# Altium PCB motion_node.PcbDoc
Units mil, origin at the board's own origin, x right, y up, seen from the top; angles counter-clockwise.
Board outline 1965 x 1965 mil, 2 copper layers (Top Layer, Bottom Layer); 90 components, 96 nets, 377 pads, 0 vias.
Unrouted connection lines stored in the file: 226.
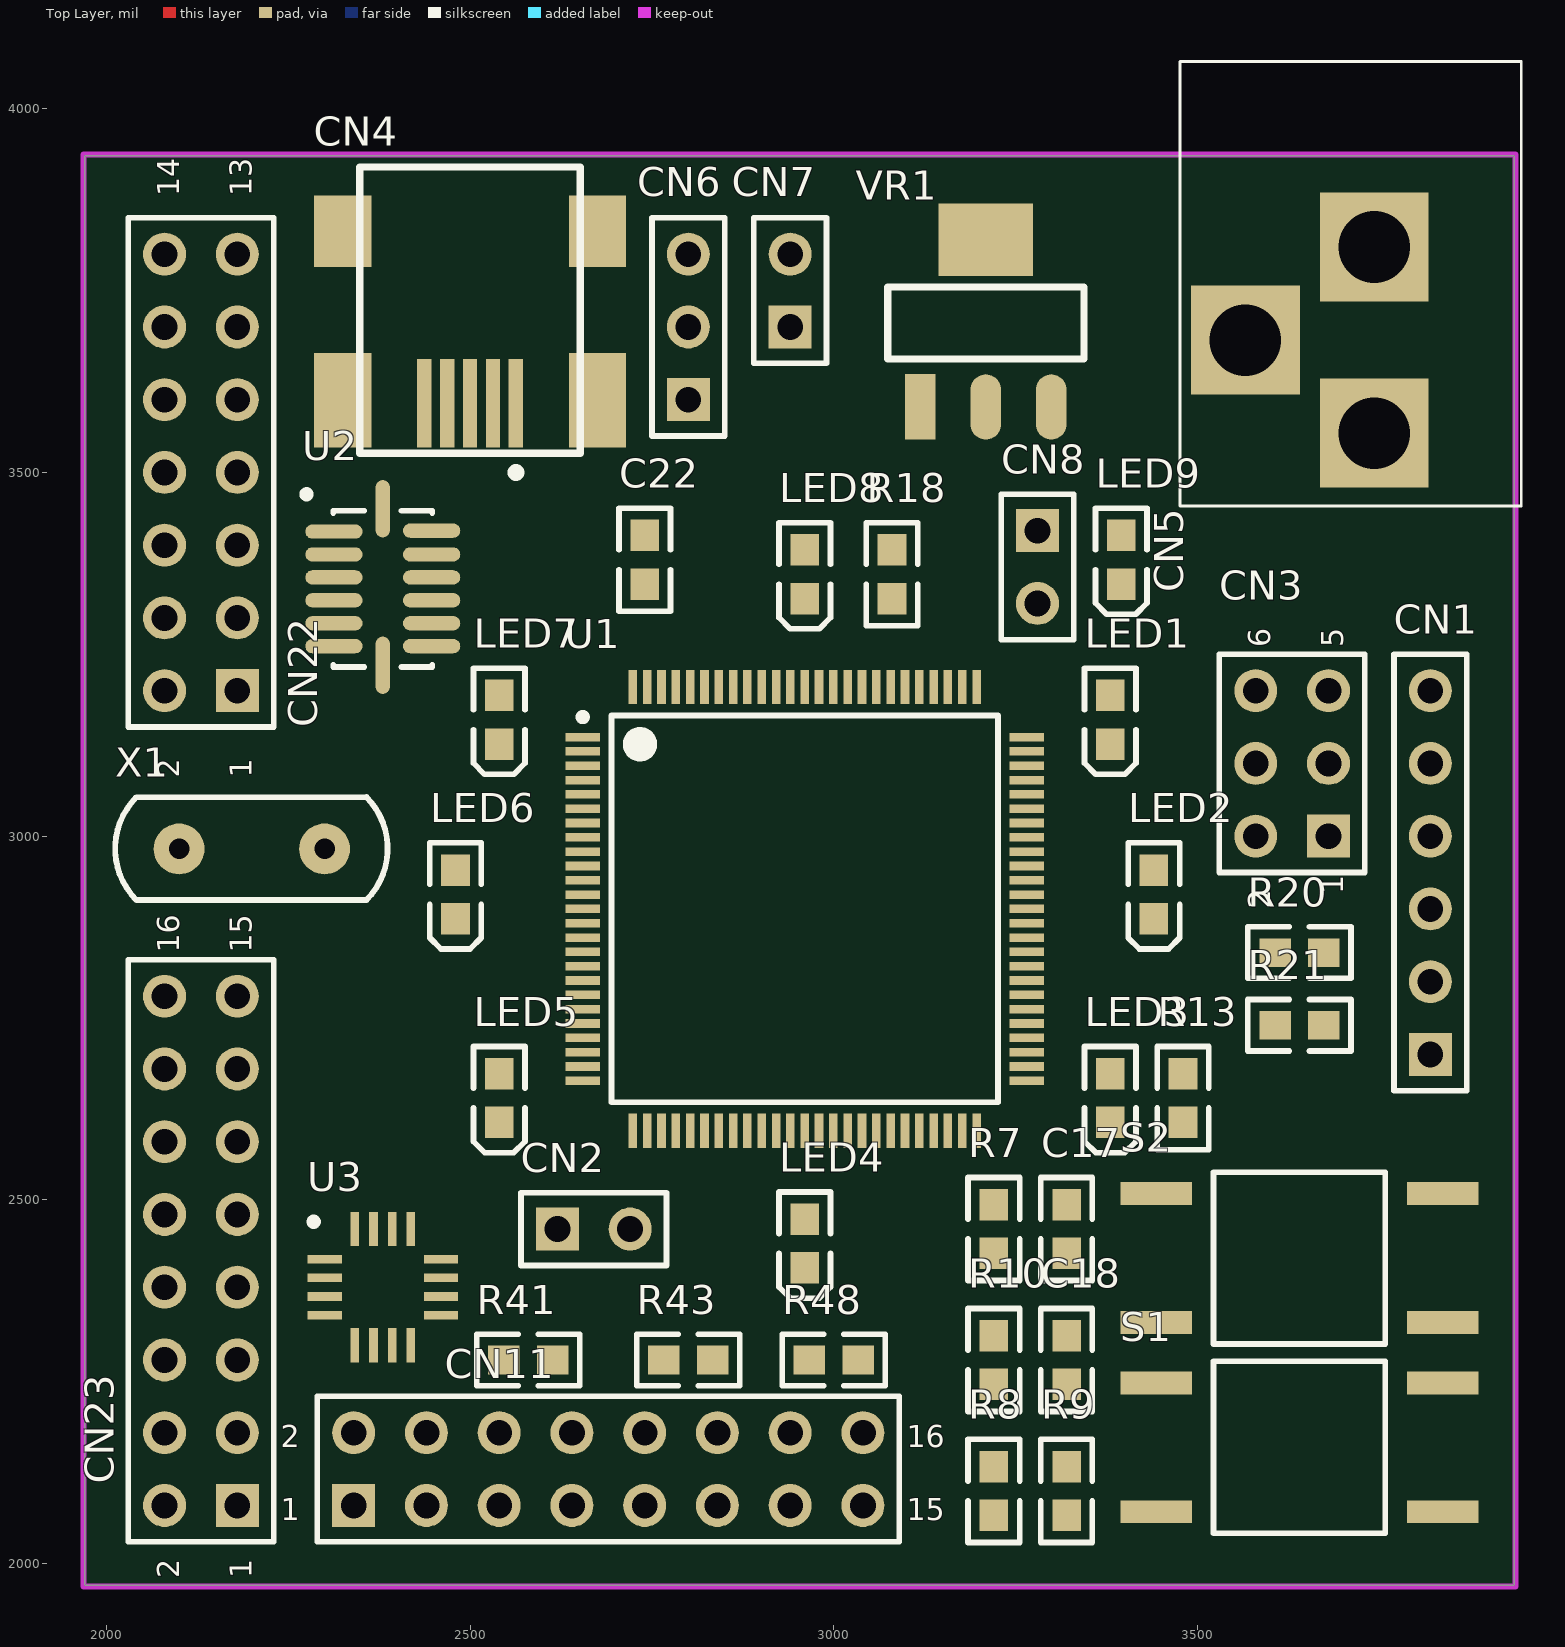
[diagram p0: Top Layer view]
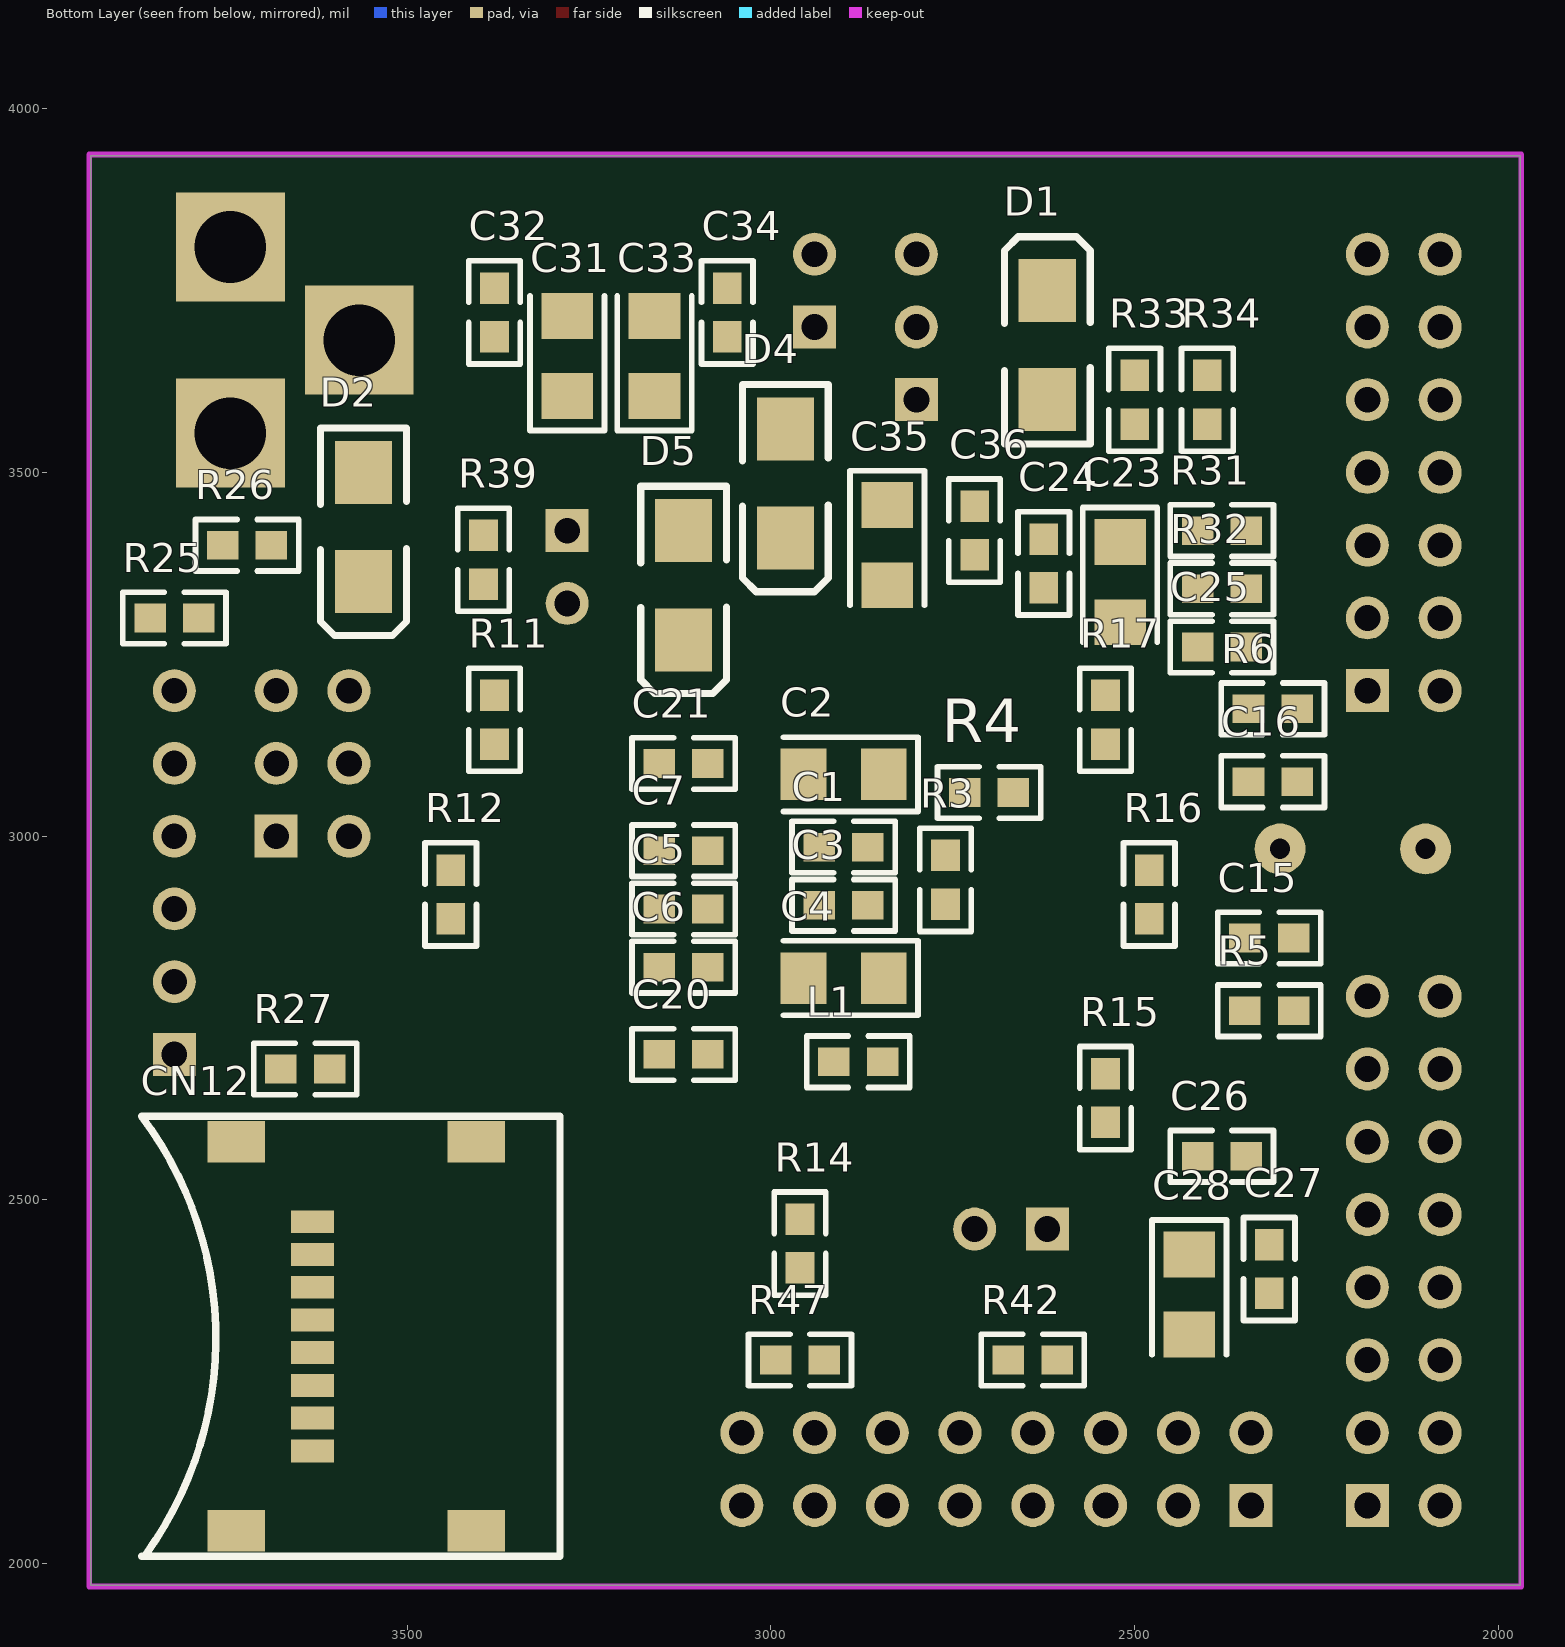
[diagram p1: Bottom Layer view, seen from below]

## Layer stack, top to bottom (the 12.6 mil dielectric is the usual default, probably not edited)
Top Layer: signal copper 1.4
Dielectric: dielectric 12.6, FR-4, Dk 4.8
Bottom Layer: signal copper 1.4

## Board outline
1970,3935 1970,1970 3935,1970 3935,3935

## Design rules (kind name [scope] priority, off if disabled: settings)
Clearance [All] p1: gap=6
ComponentClearance [All] p1: gap=0 collisioncheckmode=3 verticalgap=10 showdistances=FALSE
PolygonConnect [All] p1: connectstyle=Relief reliefconductorwidth=10 reliefentries=4 polygonreliefangle="90 Angle"
RoutingVias [All] p1: holewidth=28 width=50 viastyle="Through Hole" minholewidth=28 minwidth=50 maxholewidth=28 maxwidth=50
SilkscreenOverComponentPads [All] p1: minsilkscreentomaskgap=10
SolderMaskExpansion [All] p1: expansion=4
Width [All] p1: maxlimit=40 minlimit=6 preferedwidth=6
26 further rules are at their usual default settings.

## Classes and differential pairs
net class LED[8..1]: LED1 LED2 LED3 LED4 LED5 LED6 LED7 LED8
component class stm32f407: C1 C2 C3 C4 C5 C6 C7 C15 C16 C17 C18 C20 C21 CN1 CN2 CN3 L1 R3 R4 R5 R6 R7 R8 R9 R10 R20 R21 R25 R26 R27 S1 S2 U1 X1
component class sensors: C22 C23 C24 C25 C26 C27 C28 CN22 CN23 R31 R32 U2 U3
component class power: C31 C32 C33 C34 C35 C36 CN4 CN5 CN6 CN7 CN8 D1 D2 D4 D5 LED9 R33 R34 R39 VR1
component class others: CN11 CN12 LED1 LED2 LED3 LED4 LED5 LED6 LED7 LED8 R11 R12 R13 R14 R15 R16 R17 R18 R41 R42 R43 R47 R48

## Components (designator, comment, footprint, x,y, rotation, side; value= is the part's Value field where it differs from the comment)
C1 "Cap Semi" C1608-0603 2900,2985 r180 bottom
C2 "Cap Pol3" CC3216-1206 2900,3085 r0 bottom
C3 "Cap Semi" C1608-0603 2900,2905 r180 bottom
C4 "Cap Pol3" CC3216-1206 2900,2805 r0 bottom
C5 "Cap Semi" C1608-0603 3120,2900 r0 bottom
C6 "Cap Semi" C1608-0603 3120,2820 r0 bottom
C7 "Cap Semi" C1608-0603 3120,2980 r0 bottom
C15 "Cap Semi" C1608-0603 2315,2860 r180 bottom
C16 "Cap Semi" C1608-0603 2310,3075 r180 bottom
C17 "Cap Semi" C1608-0603 3320,2460 r270 top
C18 "Cap Semi" C1608-0603 3320,2280 r90 top
C20 "Cap Semi" C1608-0603 3120,2700 r0 bottom
C21 "Cap Semi" C1608-0603 3120,3100 r0 bottom
C22 "Cap Semi" C1608-0603 2740,3380 r270 top
C23 "Cap Pol3" CC3216-1206 2520,3349.31 r270 bottom
C24 "Cap Semi" C1608-0603 2625,3375 r270 bottom
C25 "Cap Semi" C1608-0603 2380,3260 r0 bottom
C26 "Cap Semi" C1608-0603 2380,2560 r180 bottom
C27 "Cap Semi" C1608-0603 2315,2405 r270 bottom
C28 "Cap Pol3" CC3216-1206 2425,2370 r270 bottom
C31 "Cap Pol3" CC3216-1206 3280,3660 r90 bottom
C32 "Cap Semi" C1608-0603 3380,3720 r270 bottom
C33 "Cap Pol3" CC3216-1206 3160,3660 r90 bottom
C34 "Cap Semi" C1608-0603 3060,3720 r270 bottom
C35 "Cap Pol3" CC3216-1206 2840,3400 r270 bottom
C36 "Cap Semi" C1608-0603 2720,3420 r90 bottom
CN1 "Header 6" HDR1X6 3820,2700 r90 top
CN2 "Header 2" HDR1X2 2620,2460 r0 top
CN3 "Header 3X2" HDR2X3 3680,3000 r90 top
CN4 "mini USB Type B" "mini USB Type B" 2500,3920 r180 top
CN5 "Power_Jack" POWER_JACK 3700,3840 r90 top
CN6 "Header 3" HDR1X3 2800,3600 r90 top
CN7 "Header 2" HDR1X2 2940,3700 r90 top
CN8 "Header 2" HDR1X2 3280,3420 r270 top
CN11 "Header 8X2" HDR2X8 2340,2080 r0 top
CN12 "micro SD" "micro SD" 3520,2320 r0 bottom
CN22 "Header 7X2" HDR2X7 2180,3200 r90 top
CN23 "Header 8X2" HDR2X8 2180,2080 r90 top
D1 "Diode" IN5817 2520,3600 r90 bottom
D2 "Diode" IN5817 3660,3500 r270 bottom
D4 "Diode" IN5817 3080,3560 r270 bottom
D5 "Diode" IN5817 3220,3420 r270 bottom
L1 "Inductor" R1608-0603 2880,2690 r180 bottom
LED1 "" D1608-0603 3380,3160 r270 top
LED2 "" D1608-0603 3440,2920 r270 top
LED3 "" D1608-0603 3380,2640 r270 top
LED4 "" D1608-0603 2960,2440 r270 top
LED5 "" D1608-0603 2540,2640 r270 top
LED6 "" D1608-0603 2480,2920 r270 top
LED7 "" D1608-0603 2540,3160 r270 top
LED8 "" D1608-0603 2960,3360 r270 top
LED9 "" D1608-0603 3395,3380 r270 top
R3 "Res Semi" R1608-0603 2760,2940 r270 bottom
R4 "Res Semi" R1608-0603 2700,3060 r180 bottom
R5 "Res Semi" R1608-0603 2315,2760 r180 bottom
R6 "Res Semi" R1608-0603 2310,3175 r180 bottom
R7 "Res Semi" R1608-0603 3220,2460 r270 top
R8 "Res Semi" R1608-0603 3220,2100 r90 top
R9 "Res Semi" R1608-0603 3320,2100 r270 top
R10 "Res Semi" R1608-0603 3220,2280 r270 top
R11 "Res Semi" R1608-0603 3380,3160 r90 bottom
R12 "Res Semi" R1608-0603 3440,2920 r90 bottom
R13 "Res Semi" R1608-0603 3480,2640 r90 top
R14 "Res Semi" R1608-0603 2960,2440 r90 bottom
R15 "Res Semi" R1608-0603 2540,2640 r90 bottom
R16 "Res Semi" R1608-0603 2480,2920 r90 bottom
R17 "Res Semi" R1608-0603 2540,3160 r90 bottom
R18 "Res Semi" R1608-0603 3080,3360 r90 top
R20 "Res Semi" R1608-0603 3640,2840 r180 top
R21 "Res Semi" R1608-0603 3640,2740 r180 top
R25 "Res Semi" R1608-0603 3820,3300 r180 bottom
R26 "Res Semi" R1608-0603 3720,3400 r0 bottom
R27 "Res Semi" R1608-0603 3640,2680 r180 bottom
R31 "Res Semi" R1608-0603 2380,3420 r180 bottom
R32 "Res Semi" R1608-0603 2380,3340 r180 bottom
R33 "Res Semi" R1608-0603 2500,3600 r270 bottom
R34 "Res Semi" R1608-0603 2400,3600 r270 bottom
R39 "Res Semi" R1608-0603 3395,3380 r90 bottom
R41 "Res Semi" R1608-0603 2580,2280 r180 top
R42 "Res Semi" R1608-0603 2640,2280 r180 bottom
R43 "Res Semi" R1608-0603 2800,2280 r180 top
R47 "Res Semi" R1608-0603 2960,2280 r0 bottom
R48 "Res Semi" R1608-0603 3000,2280 r180 top
S1 "Switch6X6" Switch6X6 3640,2160 r0 top
S2 "Switch6X6" Switch6X6 3640,2420 r0 top
U1 "STM32F407VGT6" LQFP100_V 2960,2900 r0 top locked
U2 "LSM303DLHC" LGA14-3X5X1_N 2380,3340 r0 top locked
U3 "L3GD20" LGA16-4X4X1 2380,2380 r0 top locked
VR1 "AMS1117" AMS1117 3260,3840 r90 top
X1 "8MHz" XTAL-0.2 2180,3140 r0 top

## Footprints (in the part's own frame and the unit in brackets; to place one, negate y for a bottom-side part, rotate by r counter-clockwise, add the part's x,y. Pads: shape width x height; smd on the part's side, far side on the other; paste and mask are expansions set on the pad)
AMS1117 [mil]
  rect 90x42 smd: 1(-250,141)
  oval 90x42 smd: 2(-250,51) 3(-250,-39)
  rect 100x130 smd: 4(-20,51)
  silkscreen extent -184,-84 -85,186
C1608-0603 [mm]
  rect 1.1x1 smd: 1(-0.85,0) 2(0.85,0)
  silkscreen extent -1.8,-0.9 1.8,0.9
CC3216-1206 [mm]
  rect 1.6x1.8 smd: 1(-1.4,0) 2(1.4,0)
  silkscreen extent -2.6,-1.3 2.1,1.3
D1608-0603 [mm]
  rect 1.1x1 smd: 1(-0.85,0) 2(0.85,0)
  silkscreen extent -1.8,-0.9 1.91,0.9
HDR1X2 [mm] "Connector; Header; 2 Position"
  rect 1.5x1.5 hole 0.9: 1(0,0)
  round 1.5 hole 0.9: 2(2.54,0)
  silkscreen extent -1.27,-1.27 3.81,1.27
HDR1X3 [mm] "Connector; Header; 3 Position"
  rect 1.5x1.5 hole 0.9: 1(0,0)
  round 1.5 hole 0.9: 2(2.54,0) 3(5.08,0)
  silkscreen extent -1.27,-1.27 6.35,1.27
HDR1X6 [mm] "Connector; Header; 6 Position"
  rect 1.5x1.5 hole 0.9: 1(0,0)
  round 1.5 hole 0.9: 2(2.54,0) 3(5.08,0) 4(7.62,0) 5(10.16,0) 6(12.7,0)
  silkscreen extent -1.27,-1.27 13.97,1.27
HDR2X3 [mm] "Connector; Header; 3x2 Position"
  rect 1.5x1.5 hole 0.9: 1(0,0)
  round 1.5 hole 0.9: 2(0,2.54) 3(2.54,0) 4(2.54,2.54) 5(5.08,0) 6(5.08,2.54)
  silkscreen extent -1.27,-1.27 6.35,3.81
HDR2X7 [mm] "Connector; Header; 7x2 Position"
  rect 1.5x1.5 hole 0.9: 1(0,0)
  round 1.5 hole 0.9: 2(0,2.54) 3(2.54,0) 4(2.54,2.54) 5(5.08,0) 6(5.08,2.54) 7(7.62,0) 8(7.62,2.54) 9(10.16,0) 10(10.16,2.54) 11(12.7,0) 12(12.7,2.54) 13(15.24,0) 14(15.24,2.54)
  silkscreen extent -1.27,-1.27 16.51,3.81
HDR2X8 [mm] "Connector; Header; 8x2 Position"
  rect 1.5x1.5 hole 0.9: 1(0,0)
  round 1.5 hole 0.9: 2(0,2.54) 3(2.54,0) 4(2.54,2.54) 5(5.08,0) 6(5.08,2.54) 7(7.62,0) 8(7.62,2.54) 9(10.16,0) 10(10.16,2.54) 11(12.7,0) 12(12.7,2.54) 13(15.24,0) 14(15.24,2.54) 15(17.78,0) 16(17.78,2.54)
  silkscreen extent -1.27,-1.27 19.05,3.81
IN5817 [mm]
  rect 2.2x2 smd: 1(0,2.54) 2(3.81,2.54)
  silkscreen extent -1.55,1.04 5.69,4.04
LGA14-3X5X1_N [mm] "PQFN, 14-Leads, Body 3x5mm, Pitch 0.8mm, IPC Medium Density"
  oval 2x0.5 smd: 1(-1.706,2) 2(-1.706,1.2) 3(-1.706,0.4) 4(-1.706,-0.4) 5(-1.706,-1.2) 6(-1.706,-2) 8(1.706,-2) 9(1.706,-1.2) 10(1.706,-0.4) 11(1.706,0.4) 12(1.706,1.2) 13(1.706,2.032)
  oval 0.5x2 smd: 7(0,-2.667) 14(0,2.794)
  silkscreen extent -2.79,-2.72 1.73,3.43, body extent -1.57,-2.57 1.58,2.58, height 1
LGA16-4X4X1 [mm]
  rect 1.2x0.3 smd: 1(-2.032,0.975) 2(-2.032,0.325) 3(-2.032,-0.325) 4(-2.032,-0.975) 9(2.032,-0.975) 10(2.032,-0.325) 11(2.032,0.325) 12(2.032,0.975)
  rect 0.3x1.2 smd: 5(-0.975,-2.032) 6(-0.325,-2.032) 7(0.325,-2.032) 8(0.975,-2.032) 13(0.975,2.032) 14(0.325,2.032) 15(-0.325,2.032) 16(-0.975,2.032)
  silkscreen extent -2.54,2.16 -2.29,2.41
LQFP100_V [mm] "Thin QFP, 100-Leads, Body 14x14mm, Pitch 0.5mm, ST Recommended"
  rect 1.2x0.3 smd: 1(-7.75,6) 2(-7.75,5.5) 3(-7.75,5) 4(-7.75,4.5) 5(-7.75,4) 6(-7.75,3.5) 7(-7.75,3) 8(-7.75,2.5) 9(-7.75,2) 10(-7.75,1.5) 11(-7.75,1) 12(-7.75,0.5) 13(-7.75,0) 14(-7.75,-0.5) 15(-7.75,-1) 16(-7.75,-1.5) 17(-7.75,-2) 18(-7.75,-2.5) 19(-7.75,-3) 20(-7.75,-3.5) 21(-7.75,-4) 22(-7.75,-4.5) 23(-7.75,-5) 24(-7.75,-5.5) 25(-7.75,-6) 51(7.75,-6) 52(7.75,-5.5) 53(7.75,-5) 54(7.75,-4.5) 55(7.75,-4) 56(7.75,-3.5) 57(7.75,-3) 58(7.75,-2.5) 59(7.75,-2) 60(7.75,-1.5) 61(7.75,-1) 62(7.75,-0.5) 63(7.75,0) 64(7.75,0.5) 65(7.75,1) 66(7.75,1.5) 67(7.75,2) 68(7.75,2.5) 69(7.75,3) 70(7.75,3.5) 71(7.75,4) 72(7.75,4.5) 73(7.75,5) 74(7.75,5.5) 75(7.75,6)
  rect 0.3x1.2 smd: 26(-6,-7.75) 27(-5.5,-7.75) 28(-5,-7.75) 29(-4.5,-7.75) 30(-4,-7.75) 31(-3.5,-7.75) 32(-3,-7.75) 33(-2.5,-7.75) 34(-2,-7.75) 35(-1.5,-7.75) 36(-1,-7.75) 37(-0.5,-7.75) 38(0,-7.75) 39(0.5,-7.75) 40(1,-7.75) 41(1.5,-7.75) 42(2,-7.75) 43(2.5,-7.75) 44(3,-7.75) 45(3.5,-7.75) 46(4,-7.75) 47(4.5,-7.75) 48(5,-7.75) 49(5.5,-7.75) 50(6,-7.75) 76(6,7.75) 77(5.5,7.75) 78(5,7.75) 79(4.5,7.75) 80(4,7.75) 81(3.5,7.75) 82(3,7.75) 83(2.5,7.75) 84(2,7.75) 85(1.5,7.75) 86(1,7.75) 87(0.5,7.75) 88(0,7.75) 89(-0.5,7.75) 90(-1,7.75) 91(-1.5,7.75) 92(-2,7.75) 93(-2.5,7.75) 94(-3,7.75) 95(-3.5,7.75) 96(-4,7.75) 97(-4.5,7.75) 98(-5,7.75) 99(-5.5,7.75) 100(-6,7.75)
  silkscreen extent -7.87,-6.75 6.75,6.82, body extent -7,-7 7,7, height 1.6
"micro SD" [mm]
  rect 1.5x0.8 smd: 1(2.794,4.191) 2(2.794,3.048) 3(2.794,1.905) 4(2.794,0.762) 5(2.794,-0.381) 6(2.794,-1.524) 7(2.794,-2.667) 8(2.794,-3.81)
  rect 2x1.45 smd: ""(-2.921,-6.604) ""(-2.921,6.985) ""(5.461,-6.604) ""(5.461,6.985)
  silkscreen extent -5.84,-7.49 8.76,7.87
"mini USB Type B" [mm]
  rect 0.5x3.1 smd: 1(-1.6,8.25) 2(-0.8,8.25) 3(0,8.25) 4(0.8,8.25) 5(1.6,8.25)
  rect 2x3.3 smd: 6(4.45,8.15) 8(-4.45,8.15)
  rect 2x2.5 smd: 7(4.45,2.25) 9(-4.45,2.25)
  silkscreen extent -3.85,0 3.85,10.81
POWER_JACK [mm]
  rect 3.8x3.8 hole 2.5: 1(-7.264,-1.092) 2(-0.764,-1.092) 3(-4.014,3.408)
  silkscreen extent -9.8,-6.22 5.72,5.69
R1608-0603 [mm]
  rect 1.1x1 smd: 1(-0.85,0) 2(0.85,0)
  silkscreen extent -1.8,-0.9 1.8,0.9
Switch6X6 [mm]
  rect 2.5x0.8 smd: 1(-5,2.25) 2(5,2.25) 3(-5,-2.25) 4(5,-2.25)
  silkscreen extent -3,-3 3,3
XTAL-0.2 [mil]
  round 70 hole 28: 1(-79.92,-157.48) 2(120.08,-157.48)
  silkscreen extent -168,-228 207,-86

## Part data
C1 C3 C5 C6 C7 C15 C16 C17 C18 C20 C21 C22 C24 C25 C26 C27 C32 C34 C36: "Capacitor (Semiconductor SIM Model)"
C2 C4 C23 C28 C31 C33 C35: "Polarized Capacitor (Surface Mount)"
CN1: "Header, 6-Pin"
CN2 CN7 CN8: "Header, 2-Pin"
CN3: "Header, 3-Pin, Dual row"
CN6: "Header, 3-Pin"
CN11 CN23: "Header, 8-Pin, Dual row"
CN22: "Header, 7-Pin, Dual row"
D1 D2 D4 D5: "Default Diode"
LED1 LED2 LED3 LED4 LED5 LED6 LED7 LED8 LED9: library part LED2, "Typical RED, GREEN, YELLOW, AMBER GaAs LED"
R3 R4 R5 R6 R7 R8 R9 R10 R11 R12 R13 R14 R15 R16 R17 R18 R20 R21 R25 R26 R27 R31 R32 R33 R34 R39 R41 R42 R43 R47 R48: "Semiconductor Resistor"
S1 S2: "Switch"
VR1: "Voltage Regulator"
X1: library part XTAL, "Crystal Oscillator"

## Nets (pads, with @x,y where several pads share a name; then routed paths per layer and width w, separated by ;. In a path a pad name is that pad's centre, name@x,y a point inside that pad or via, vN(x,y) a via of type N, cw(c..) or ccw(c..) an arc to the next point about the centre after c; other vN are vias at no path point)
5V: C31.1 C32.2 CN6.2 D1.2 D2.2 VR1.3
BOOT0: R20.2 U1.94
BOOT1: R21.1 U1.37
GND: C1.1 C2.2 C3.1 C4.2 C5.1 C6.1 C7.1 C15.1 C16.1 C17.2 C20.1 C21.1 C31.2 C32.1 C33.2 C34.1 C35.2 C36.1 CN1.3 CN3.5 CN3.6 CN4.5 CN4.6 CN4.7 CN4.8 CN4.9 CN5.2 CN5.3 CN6.1 CN7.2 CN11.11 CN22.13 CN23.15 R9.1 R11.2 R12.2 R13.2 R14.2 R15.2 R16.2 R17.2 R18.2 R34.1 R39.2 S2.3 S2.4 U1.10 U1.20 U1.27 U1.74 U1.99 VR1.1
JACK_5V: CN5.1 D2.1
L3GD20_CS: CN23.10 U3.5
L3GD20_GND: C26.1 C27.2 C28.2 CN23.16 U3.8 U3.9 U3.10 U3.11 U3.12 U3.13
L3GD20_INT1: CN23.14 U3.7
L3GD20_INT2: CN23.12 U3.6
L3GD20_MISO: CN23.8 U3.4
L3GD20_MOSI: CN23.6 U3.3
L3GD20_SCK: CN23.4 U3.2
L3GD20_VDD: C27.1 C28.1 CN23.2 U3.1 U3.15 U3.16
LED1: LED1.1 U1.55
LED2: LED2.1 U1.56
LED3: LED3.1 U1.57
LED4: LED4.1 U1.58
LED5: LED5.1 U1.59
LED6: LED6.1 U1.60
LED7: LED7.1 U1.61
LED8: LED8.1 U1.62
LI_3.7V: C35.1 C36.2 CN7.1 D4.1
LSM303_DRDY: CN22.8 U2.9
LSM303_GND: C23.2 C24.2 C25.2 CN22.14 U2.7 U2.10 U2.11
LSM303_INT1: CN22.6 U2.5
LSM303_INT2: CN22.4 U2.4
LSM303_SCL: CN22.10 R31.2 U2.2
LSM303_SDA: CN22.12 R32.2 U2.3
LSM303_VDD: C23.1 C24.1 CN22.2 R31.1 R32.1 U2.1 U2.14
NetC1_2: C1.2 C2.1 R3.1 U1.21
NetC15_2: C15.2 R5.2 X1.2
NetC16_2: C16.2 R6.2 X1.1
NetC18_1: C18.1 R10.2
NetC18_2: C18.2 R8.1 R9.2 S1.3 S1.4
NetC20_2: C20.2 U1.49
NetC21_2: C21.2 U1.73
NetC22_1: C22.1 U2.13
NetC22_2: C22.2 U2.12
NetC25_1: C25.1 U2.6
NetC26_2: C26.2 U3.14
NetC33_1: C33.1 C34.2 CN8.1 VR1.2
NetCN1_1: CN1.1 R27.1
NetCN1_5: CN1.5 R25.2
NetCN1_6: CN1.6 R26.2
NetCN3_3: CN3.3 R20.1
NetCN3_4: CN3.4 R21.2
NetCN4_3: CN4.3 R33.2
NetCN4_4: CN4.4 R34.2
NetD4_2: D4.2 D5.1
NetLED1_2: LED1.2 R11.1
NetLED2_2: LED2.2 R12.1
NetLED3_2: LED3.2 R13.1
NetLED4_2: LED4.2 R14.1
NetLED5_2: LED5.2 R15.1
NetLED6_2: LED6.2 R16.1
NetLED7_2: LED7.2 R17.1
NetLED8_2: LED8.2 R18.1
NetLED9_2: LED9.2 R39.1
NetR5_1: R5.1 U1.12
NetR6_1: R6.1 U1.13
NetR8_2: R8.2 U1.23
NRST: C17.1 R7.1 R25.1 S2.1 S2.2 U1.14
PA5_SCK: CN23.3 U1.30
PA6_MISO: CN23.7 U1.31
PA7_MOSI: CN23.5 U1.32
PB6_SCL: CN22.9 U1.92
PB7_SDA: CN22.11 U1.93
PC8: CN11.13 U1.65
PC9: CN11.15 U1.66
PC10: CN11.1 U1.78
PC11: CN11.3 U1.79
PC12: CN11.9 U1.80
PD2: CN11.5 U1.83
PE0_INT1: CN23.13 U1.97
PE1_INT2: CN23.11 U1.98
PE2_DRDY: CN22.7 U1.1
PE3_CS: CN23.9 U1.2
PE4_INT1: CN22.5 U1.3
PE5_INT2: CN22.3 U1.4
SD_CK: CN11.10 CN12.5
SD_CMD: CN11.6 CN12.3 R43.2
SD_D0: CN11.14 CN12.7 R47.1
SD_D1: CN11.16 CN12.8 R48.1
SD_D2: CN11.2 CN12.1 R41.2
SD_D3: CN11.4 CN12.2 R42.2
SD_GND: CN11.12 CN12.6
SD_VDD: CN11.8 CN12.4 R41.1 R42.1 R43.1 R47.2 R48.2
SWCLK: CN1.2 U1.76
SWDIO: CN1.4 U1.72
SWO: R26.1 U1.89
USART2_RX: CN2.2 U1.26
USART2_TX: CN2.1 U1.25
USB_5V: CN4.1 D1.1
VBAT: R4.2 U1.6
VDD: C5.2 C6.2 C7.2 CN3.1 CN3.2 CN6.3 CN8.2 CN11.7 CN22.1 CN23.1 D5.2 L1.2 LED9.1 R4.1 R7.2 R10.1 R27.2 R33.1 S1.1 S1.2 U1.11 U1.19 U1.28 U1.50 U1.75 U1.100
VDDA: C3.2 C4.1 L1.1 R3.2 U1.22
pads on no net: CN4.2 CN12. U1.5 U1.7 U1.8 U1.9 U1.15 U1.16 U1.17 U1.18 U1.24 U1.29 U1.33 U1.34 U1.35 U1.36 U1.38 U1.39 U1.40 U1.41 U1.42 U1.43 U1.44 U1.45 U1.46 U1.47 U1.48 U1.51 U1.52 U1.53 U1.54 U1.63 U1.64 U1.67 U1.68 U1.69 U1.70 U1.71 U1.77 U1.81 U1.82 U1.84 U1.85 U1.86 U1.87 U1.88 U1.90 U1.91 U1.95 U1.96 U2.8 VR1.4

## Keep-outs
Keep-Out Layer:
  lines w7.87: 1968.5,1968.5 1968.5,3937.01 3937.01,3937.01 3937.01,1968.5 1968.5,1968.5

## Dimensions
3937.01,3937.01 to 1968.5,3937.01 on Keep-Out Layer
1968.5,3937.01 to 1968.5,1968.5 on Keep-Out Layer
